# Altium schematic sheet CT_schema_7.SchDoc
size 388 x 278 mm
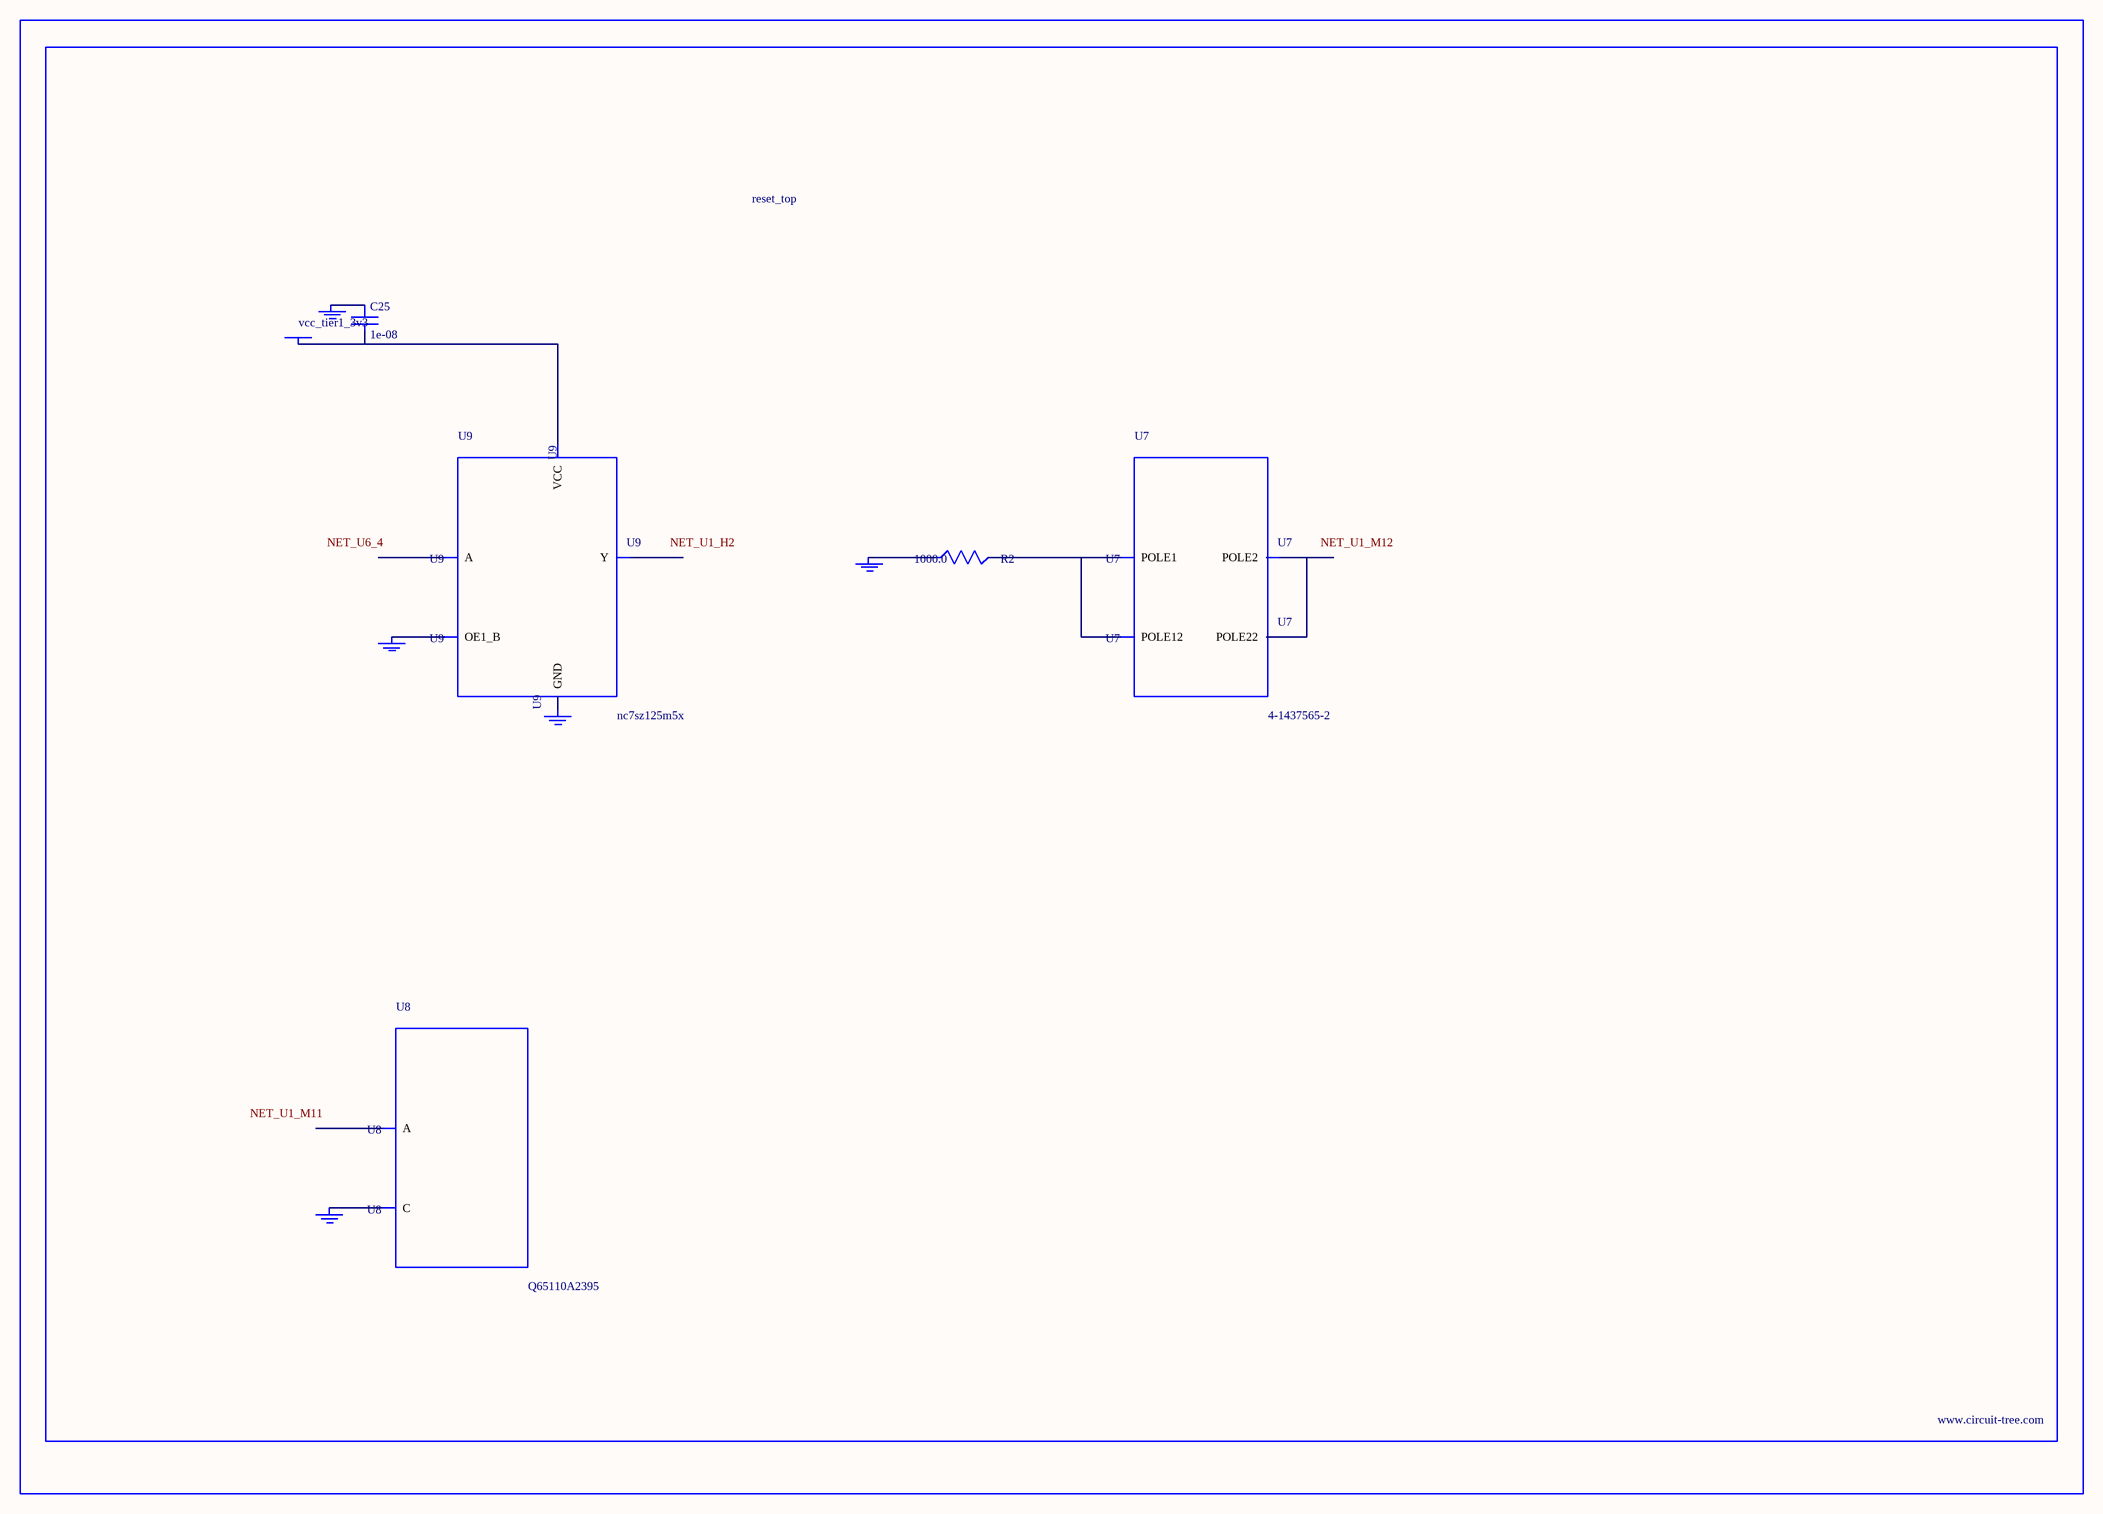
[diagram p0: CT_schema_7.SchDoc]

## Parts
BORDER6  (no value)
C25  1e-08  [C0402]
GND_INSTANCE_6_0  (no value)
GND_INSTANCE_6_1  (no value)
GND_INSTANCE_6_2  (no value)
GND_INSTANCE_6_3  (no value)
GND_INSTANCE_6_4  (no value)
POWER_INSTANCE_6_0  vcc_tier1_3v3
R2  1000.0  [R0603]
U7  4-1437565-2  [SW_4-1437565-2]
U8  Q65110A2395  [LGM67K-G1J2-24-Z]
U9  nc7sz125m5x  [NC7SZ125M5X]

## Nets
NetC25_1: C25.1 GND_INSTANCE_6_2.0(GND)
NetC25_2: C25.2 POWER_INSTANCE_6_0.0(PWR) U9.5(VCC)
NetGND_INSTANCE_6_0_0: GND_INSTANCE_6_0.0(GND) R2.1
NetGND_INSTANCE_6_1_0: GND_INSTANCE_6_1.0(GND) U8.C
NetGND_INSTANCE_6_3_0: GND_INSTANCE_6_3.0(GND) U9.1(OE1_B)
NetGND_INSTANCE_6_4_0: GND_INSTANCE_6_4.0(GND) U9.3(GND)
NetR2_2: R2.2 U7.1(POLE1) U7.2(POLE12)
NetU7_3: U7.3(POLE2) U7.4(POLE22)

Not connected (* = marked no-connect by the designer): U8 A; U9 2(A) 4(Y)

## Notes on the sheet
- Labels drawn without touching a wire or pin: NET_U1_H2, NET_U1_M11, NET_U1_M12, NET_U6_4

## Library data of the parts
BORDER6 = BORDER_PAGE6
C25 = C0402C103K3RAC
GND_INSTANCE_6_0-GND_INSTANCE_6_4 = GND
POWER_INSTANCE_6_0 = PWR
R2 = RC0603JR-071KL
